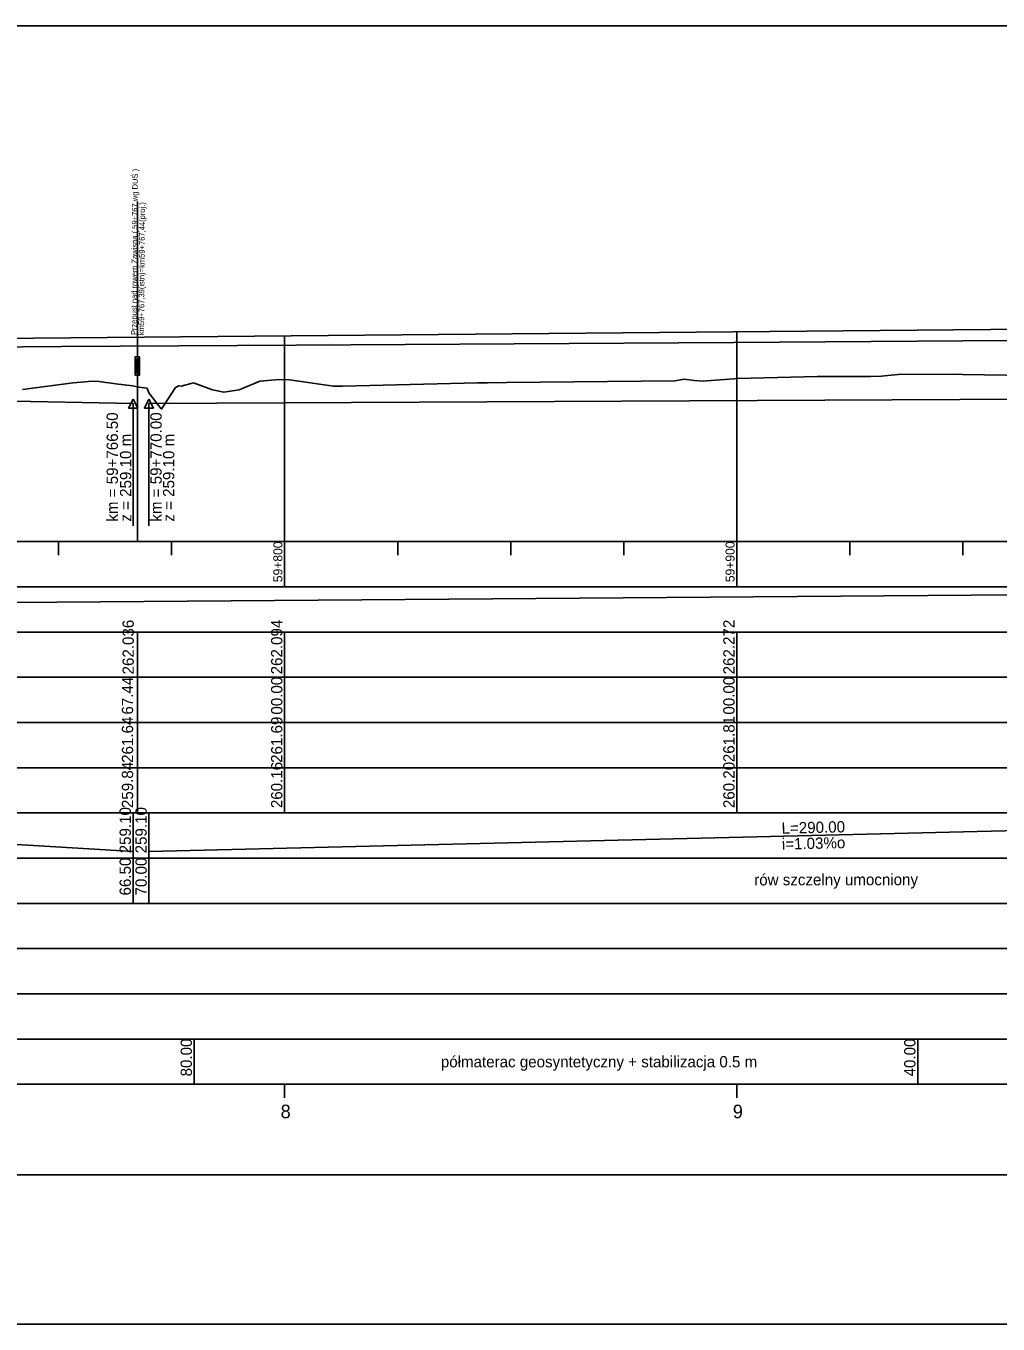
# Model space of a CAD drawing. Extents: x 6445630 to 6518227, y 5499240 to 5511716.
# Drawn here: x 6458974 to 6459189, y 5508418.3 to 5508705.3 of the extents above; entities that cross this region are included whole.
import ezdxf

# ---------------------------------------------------------------- set-up
doc = ezdxf.new("R2010")
doc.units = 0
for name, color, linetype in [('TOR_PROF-obiekty+opisy', 7, 'Continuous'), ('TOR_PROF-opisy pomocnicze', 7, 'Continuous'), ('TOR_PROF-rowy otwarte', 7, 'Continuous'), ('TOR_PROF-tabelka-geometria T1', 7, 'Continuous'), ('TOR_PROF-tabelka-kilometracja', 7, 'Continuous'), ('TOR_PROF-tabelka-odleglosci T1', 7, 'Continuous'), ('TOR_PROF-tabelka-pochylenia proj T1', 7, 'Continuous'), ('TOR_PROF-tabelka-rodzaj rowu T1', 7, 'Continuous'), ('TOR_PROF-tabelka-rowyT1', 7, 'Continuous'), ('TOR_PROF-tabelka-rurociagi T1', 7, 'Continuous'), ('TOR_PROF-tabelka-rzedne istn T1', 7, 'Continuous'), ('TOR_PROF-tabelka-rzedne proj T1', 7, 'Continuous'), ('TOR_PROF-tabelka-teren istniejacy T1', 7, 'Continuous'), ('TOR_PROF-tabelka-warstwa ochronna T1', 7, 'Continuous'), ('TOR_PROF-tor istniejacy T2', 7, 'Continuous'), ('TOR_PROF-tor projektowany', 7, 'Continuous'), ('TOR_PROF-uklad odniesienia', 7, 'Continuous'), ('TOR_PROF-warstwa ochronna', 7, 'Continuous'), ('TOR_RAMKI-dodatkowe3', 7, 'Continuous'), ('TOR_RAMKI-MASKA WYCIECIA', 7, 'Continuous')]:
    doc.layers.add(name, color=color, linetype=linetype)

msp = doc.modelspace()

# ---------------------------------------------------------------- linework, layer by layer
at = {"layer": 'TOR_PROF-obiekty+opisy'}
for p, q in [((6458998.65, 5508591.29), (6458998.65, 5508666.46)), ((6458998.65, 5508657.49), (6458998.65, 5508636.38)), ((6458998.65, 5508657.46), (6458998.65, 5508636.46)), ((6458998.65, 5508657.46), (6458998.65, 5508636.46))]:
    msp.add_line(p, q, dxfattribs=at)
for points in [[(6458999.11, 5508632.14), (6458998.19, 5508632.14), (6458998.19, 5508628.06), (6458999.11, 5508628.06)], [(6458999.03, 5508631.6), (6458998.28, 5508631.6), (6458998.28, 5508628.6), (6458999.03, 5508628.6)]]:
    msp.add_lwpolyline(points, close=True, dxfattribs=at)
for points in [[(6458999.11, 5508628.06), (6458999.11, 5508632.14), (6458998.19, 5508632.14), (6458998.19, 5508628.06), (6458999.11, 5508628.06)], [(6458999.03, 5508628.6), (6458998.28, 5508628.6), (6458998.28, 5508631.6), (6458999.03, 5508631.6), (6458999.03, 5508628.6)]]:
    msp.add_lwpolyline(points, dxfattribs=at)
at = {"layer": 'TOR_PROF-opisy pomocnicze'}
for p, q in [((6458997.71, 5508621.79), (6458997.71, 5508594.79)), ((6459001.21, 5508621.79), (6459001.21, 5508594.79))]:
    msp.add_line(p, q, dxfattribs=at)
for points in [[(6458997.71, 5508622.79), (6458998.71, 5508620.79), (6458996.71, 5508620.79)], [(6459001.21, 5508622.79), (6459002.21, 5508620.79), (6459000.21, 5508620.79)]]:
    msp.add_lwpolyline(points, close=True, dxfattribs=at)
at = {"layer": 'TOR_PROF-rowy otwarte'}
for p, q in [((6458881.21, 5508624.29), (6458997.71, 5508621.79)), ((6459001.21, 5508621.79), (6459291.21, 5508623.29))]:
    msp.add_line(p, q, dxfattribs=at)
at = {"layer": 'TOR_PROF-tabelka-geometria T1'}
for points in [[(6452331.21, 5508451.29), (6462731.21, 5508451.29)], [(6457590.67, 5508451.29), (6459780.93, 5508451.29), (6459780.93, 5508448.62), (6459865.93, 5508448.62), (6459865.93, 5508451.29), (6459945.93, 5508451.29), (6459945.93, 5508453.96), (6460030.94, 5508453.96), (6460030.94, 5508451.29), (6460430.94, 5508451.29), (6460430.94, 5508453.96), (6460512.51, 5508453.96), (6460512.51, 5508451.29), (6460592.51, 5508451.29), (6460592.51, 5508448.62), (6460674.08, 5508448.62), (6460674.08, 5508451.29), (6461733.15, 5508451.29)]]:
    msp.add_lwpolyline(points, dxfattribs=at)
at = {"layer": 'TOR_PROF-tabelka-kilometracja'}
for points in [[(6459031.21, 5508468.29), (6459031.21, 5508471.29)], [(6459131.21, 5508468.29), (6459131.21, 5508471.29)]]:
    msp.add_lwpolyline(points, dxfattribs=at)
at = {"layer": 'TOR_PROF-tabelka-odleglosci T1'}
msp.add_lwpolyline([(6452331.21, 5508551.29), (6462731.21, 5508551.29), (6462731.21, 5508561.29), (6452331.21, 5508561.29)], close=True, dxfattribs=at)
for points in [[(6458998.65, 5508551.29), (6458998.65, 5508561.29)], [(6459031.21, 5508551.29), (6459031.21, 5508561.29)], [(6459131.21, 5508551.29), (6459131.21, 5508561.29)]]:
    msp.add_lwpolyline(points, dxfattribs=at)
at = {"layer": 'TOR_PROF-tabelka-pochylenia proj T1'}
msp.add_lwpolyline([(6452331.21, 5508571.29), (6462731.21, 5508571.29), (6462731.21, 5508581.29), (6452331.21, 5508581.29)], close=True, dxfattribs=at)
msp.add_lwpolyline([(6458316.21, 5508572.79), (6459231.21, 5508579.79)], dxfattribs=at)
at = {"layer": 'TOR_PROF-tabelka-rodzaj rowu T1'}
for points in [[(6452331.21, 5508511.29), (6462731.21, 5508511.29), (6462731.21, 5508521.29), (6452331.21, 5508521.29)], [(6452331.21, 5508511.29), (6462731.21, 5508511.29), (6462731.21, 5508521.29), (6452331.21, 5508521.29)], [(6452331.21, 5508491.29), (6462731.21, 5508491.29), (6462731.21, 5508501.29), (6452331.21, 5508501.29)]]:
    msp.add_lwpolyline(points, close=True, dxfattribs=at)
for points in [[(6458997.71, 5508511.29), (6458997.71, 5508521.29)], [(6459001.21, 5508511.29), (6459001.21, 5508521.29)]]:
    msp.add_lwpolyline(points, dxfattribs=at)
at = {"layer": 'TOR_PROF-tabelka-rowyT1'}
msp.add_lwpolyline([(6452331.21, 5508521.29), (6462731.21, 5508521.29), (6462731.21, 5508531.29), (6452331.21, 5508531.29)], close=True, dxfattribs=at)
msp.add_lwpolyline([(6452331.21, 5508521.29), (6462731.21, 5508521.29), (6462731.21, 5508531.29), (6452331.21, 5508531.29)], close=True, dxfattribs=at)
msp.add_lwpolyline([(6452331.21, 5508521.29), (6462731.21, 5508521.29), (6462731.21, 5508531.29), (6452331.21, 5508531.29)], close=True, dxfattribs=at)
for points in [[(6458881.21, 5508529.79), (6458997.71, 5508522.79)], [(6458997.71, 5508521.29), (6458997.71, 5508531.29)], [(6459001.21, 5508521.29), (6459001.21, 5508531.29)], [(6459001.21, 5508522.79), (6459291.21, 5508529.79)]]:
    msp.add_lwpolyline(points, dxfattribs=at)
at = {"layer": 'TOR_PROF-tabelka-rurociagi T1'}
msp.add_lwpolyline([(6452331.21, 5508501.29), (6462731.21, 5508501.29), (6462731.21, 5508511.29), (6452331.21, 5508511.29)], close=True, dxfattribs=at)
at = {"layer": 'TOR_PROF-tabelka-rzedne istn T1'}
msp.add_lwpolyline([(6452331.21, 5508541.29), (6462731.21, 5508541.29), (6462731.21, 5508551.29), (6452331.21, 5508551.29)], close=True, dxfattribs=at)
for points in [[(6458998.65, 5508541.29), (6458998.65, 5508551.29)], [(6459031.21, 5508541.29), (6459031.21, 5508551.29)], [(6459131.21, 5508541.29), (6459131.21, 5508551.29)], [(6458998.65, 5508531.29), (6458998.65, 5508541.29)], [(6459031.21, 5508531.29), (6459031.21, 5508541.29)], [(6459031.21, 5508531.29), (6459031.21, 5508541.29)], [(6459031.21, 5508531.29), (6459031.21, 5508541.29)], [(6459031.21, 5508531.29), (6459031.21, 5508541.29)], [(6459131.21, 5508531.29), (6459131.21, 5508541.29)], [(6459131.21, 5508531.29), (6459131.21, 5508541.29)], [(6459131.21, 5508531.29), (6459131.21, 5508541.29)], [(6459131.21, 5508531.29), (6459131.21, 5508541.29)]]:
    msp.add_lwpolyline(points, dxfattribs=at)
at = {"layer": 'TOR_PROF-tabelka-rzedne proj T1'}
msp.add_lwpolyline([(6452331.21, 5508561.29), (6462731.21, 5508561.29), (6462731.21, 5508571.29), (6452331.21, 5508571.29)], close=True, dxfattribs=at)
for points in [[(6458998.65, 5508561.29), (6458998.65, 5508571.29)], [(6459031.21, 5508561.29), (6459031.21, 5508571.29)], [(6459131.21, 5508561.29), (6459131.21, 5508571.29)]]:
    msp.add_lwpolyline(points, dxfattribs=at)
at = {"layer": 'TOR_PROF-tabelka-teren istniejacy T1'}
msp.add_lwpolyline([(6452331.21, 5508531.29), (6462731.21, 5508531.29), (6462731.21, 5508541.29), (6452331.21, 5508541.29)], close=True, dxfattribs=at)
msp.add_lwpolyline([(6452331.21, 5508531.29), (6462731.21, 5508531.29), (6462731.21, 5508541.29), (6452331.21, 5508541.29)], close=True, dxfattribs=at)
msp.add_lwpolyline([(6452331.21, 5508531.29), (6462731.21, 5508531.29), (6462731.21, 5508541.29), (6452331.21, 5508541.29)], close=True, dxfattribs=at)
msp.add_lwpolyline([(6452331.21, 5508531.29), (6462731.21, 5508531.29), (6462731.21, 5508541.29), (6452331.21, 5508541.29)], close=True, dxfattribs=at)
at = {"layer": 'TOR_PROF-tabelka-warstwa ochronna T1'}
msp.add_lwpolyline([(6452331.21, 5508481.29), (6462731.21, 5508481.29), (6462731.21, 5508491.29), (6452331.21, 5508491.29)], close=True, dxfattribs=at)
at = {"layer": 'TOR_PROF-tor istniejacy T2'}
msp.add_lwpolyline([(6459879.79, 5508639.74), (6459830.31, 5508639.59), (6459780.15, 5508639.54), (6459763.47, 5508639.39), (6459730.24, 5508639.29), (6459680.5, 5508639.29), (6459630.51, 5508639.04), (6459597.28, 5508638.79), (6459591.3, 5508638.74), (6459558.07, 5508638.59), (6459530.72, 5508638.59), (6459509.57, 5508638.34), (6459476.34, 5508637.94), (6459430.67, 5508637.54), (6459381.22, 5508637.14), (6459331.37, 5508636.74), (6459281.19, 5508636.39), (6459231.27, 5508636.04), (6459181.17, 5508635.64), (6459130.56, 5508635.34), (6459081.98, 5508635.04), (6459033.74, 5508634.74), (6458981.86, 5508634.39), (6458930.5, 5508633.99)], dxfattribs=at)
at = {"layer": 'TOR_PROF-tor projektowany'}
msp.add_line((6458316.21, 5508630.39), (6459231.21, 5508638.54), dxfattribs=at)
msp.add_line((6458316.21, 5508630.39), (6459231.21, 5508638.54), dxfattribs=at)
for points in [[(6459031.21, 5508636.76), (6459031.21, 5508596.29), (6459031.21, 5508591.29), (6459031.21, 5508591.29)], [(6459031.21, 5508636.76), (6459031.21, 5508596.29), (6459031.21, 5508591.29), (6459031.21, 5508591.29)], [(6459131.21, 5508637.65), (6459131.21, 5508596.29), (6459131.21, 5508591.29), (6459131.21, 5508591.29)], [(6459131.21, 5508637.65), (6459131.21, 5508596.29), (6459131.21, 5508591.29), (6459131.21, 5508591.29)]]:
    msp.add_lwpolyline(points, dxfattribs=at)
at = {"layer": 'TOR_PROF-uklad odniesienia'}
for p, q in [((6452331.21, 5508591.29), (6462731.21, 5508591.29)), ((6452331.21, 5508591.29), (6462731.21, 5508591.29)), ((6458981.21, 5508588.29), (6458981.21, 5508591.29)), ((6458981.21, 5508588.29), (6458981.21, 5508591.29)), ((6459006.21, 5508588.29), (6459006.21, 5508591.29)), ((6459006.21, 5508588.29), (6459006.21, 5508591.29)), ((6459031.21, 5508581.29), (6459031.21, 5508591.29)), ((6459031.21, 5508581.29), (6459031.21, 5508591.29)), ((6459056.21, 5508588.29), (6459056.21, 5508591.29)), ((6459056.21, 5508588.29), (6459056.21, 5508591.29)), ((6459081.21, 5508588.29), (6459081.21, 5508591.29)), ((6459081.21, 5508588.29), (6459081.21, 5508591.29)), ((6459106.21, 5508588.29), (6459106.21, 5508591.29)), ((6459106.21, 5508588.29), (6459106.21, 5508591.29)), ((6459131.21, 5508581.29), (6459131.21, 5508591.29)), ((6459131.21, 5508581.29), (6459131.21, 5508591.29)), ((6459156.21, 5508588.29), (6459156.21, 5508591.29)), ((6459156.21, 5508588.29), (6459156.21, 5508591.29)), ((6459181.21, 5508588.29), (6459181.21, 5508591.29)), ((6459181.21, 5508588.29), (6459181.21, 5508591.29))]:
    msp.add_line(p, q, dxfattribs=at)
at = {"layer": 'TOR_PROF-warstwa ochronna'}
msp.add_lwpolyline([(6452331.21, 5508471.29), (6462731.21, 5508471.29), (6462731.21, 5508481.29), (6452331.21, 5508481.29)], close=True, dxfattribs=at)
for points in [[(6459011.21, 5508471.29), (6459011.21, 5508481.29)], [(6459171.21, 5508471.29), (6459171.21, 5508481.29)]]:
    msp.add_lwpolyline(points, dxfattribs=at)
at = {"layer": 'TOR_RAMKI-dodatkowe3'}
for p, q in [((6458973.22, 5508624.93), (6458984.45, 5508626.36)), ((6458984.45, 5508626.36), (6458988.75, 5508626.74)), ((6458988.75, 5508626.74), (6458990.2, 5508626.7)), ((6458990.2, 5508626.7), (6458993.85, 5508626.16)), ((6459008.36, 5508625.63), (6459011.05, 5508626.37)), ((6459011.05, 5508626.37), (6459015.23, 5508624.82)), ((6459021.13, 5508624.85), (6459025.69, 5508626.79)), ((6459025.69, 5508626.79), (6459030.07, 5508627.14)), ((6459030.07, 5508627.14), (6459032.27, 5508627.07)), ((6459032.27, 5508627.07), (6459041.98, 5508625.68)), ((6459044.11, 5508625.68), (6459073.86, 5508626.35)), ((6459073.86, 5508626.35), (6459076.08, 5508626.4)), ((6459076.08, 5508626.4), (6459077.05, 5508626.45)), ((6459077.05, 5508626.45), (6459078.23, 5508626.42)), ((6459078.23, 5508626.42), (6459080.25, 5508626.49)), ((6459080.25, 5508626.49), (6459117.49, 5508626.82)), ((6459117.49, 5508626.82), (6459119.66, 5508627.19)), ((6459119.66, 5508627.19), (6459121.75, 5508626.88)), ((6459121.75, 5508626.88), (6459123.75, 5508626.78)), ((6459123.75, 5508626.78), (6459124.51, 5508626.83)), ((6459124.51, 5508626.83), (6459130.52, 5508627.24)), ((6459130.52, 5508627.24), (6459131.39, 5508627.33)), ((6459131.39, 5508627.33), (6459149.06, 5508627.79)), ((6459149.06, 5508627.79), (6459153.77, 5508627.79)), ((6459153.77, 5508627.79), (6459160.8, 5508627.79)), ((6459160.8, 5508627.79), (6459163.22, 5508627.84)), ((6459163.22, 5508627.84), (6459164.62, 5508627.98)), ((6459164.62, 5508627.98), (6459166.9, 5508628.2)), ((6459166.9, 5508628.2), (6459178.92, 5508628.28)), ((6459178.92, 5508628.28), (6459181.16, 5508628.22)), ((6459181.16, 5508628.22), (6459195.5, 5508627.98)), ((6458993.85, 5508626.16), (6458997.55, 5508625.71)), ((6458997.55, 5508625.71), (6458998.98, 5508625.45)), ((6458998.98, 5508625.45), (6459000.79, 5508625.19)), ((6459000.79, 5508625.19), (6459001.17, 5508624.17)), ((6459001.17, 5508624.17), (6459003.64, 5508621)), ((6459004.37, 5508621.16), (6459007.05, 5508625.34)), ((6459007.05, 5508625.34), (6459007.78, 5508625.72)), ((6459007.78, 5508625.72), (6459008.36, 5508625.63)), ((6459015.23, 5508624.82), (6459017.78, 5508624.32)), ((6459017.78, 5508624.32), (6459021.13, 5508624.85)), ((6459041.98, 5508625.68), (6459042.43, 5508625.64)), ((6459042.43, 5508625.64), (6459042.94, 5508625.64)), ((6459042.94, 5508625.64), (6459044.11, 5508625.68)), ((6459003.64, 5508621), (6459003.94, 5508620.67)), ((6459003.94, 5508620.67), (6459003.99, 5508620.58)), ((6459003.99, 5508620.58), (6459004.37, 5508621.16))]:
    msp.add_line(p, q, dxfattribs=at)
at = {"layer": 'TOR_RAMKI-MASKA WYCIECIA'}
msp.add_lwpolyline([(6457196.67, 5508418.29), (6459246.67, 5508418.29), (6459246.67, 5508705.29), (6457196.67, 5508705.29)], close=True, dxfattribs=at)

# ---------------------------------------------------------------- texts
at = {"layer": 'TOR_PROF-obiekty+opisy'}
for s, p in [('Przepust nad rowem Zawisna ( 59+767 wg DUŚ )', (6458998.5, 5508636.94)), ('km59+767,39(istn)=km59+767,44(proj.)', (6459000.12, 5508636.92))]:
    msp.add_text(s, height=1.25, rotation=89.5846, dxfattribs=at).set_placement(p)
at = {"layer": 'TOR_PROF-opisy pomocnicze'}
for s, p in [('km = 59+766.50', (6458994.34, 5508595.69)), ('km = 59+770.00', (6459004.02, 5508595.69)), ('z = 259.10 m', (6458997.3, 5508595.69)), ('z = 259.10 m', (6459006.81, 5508595.69))]:
    msp.add_text(s, height=2.5, rotation=90, dxfattribs=at).set_placement(p)
at = {"layer": 'TOR_PROF-tabelka-kilometracja'}
for s, p in [('8', (6459030.32, 5508463.79)), ('9', (6459130.32, 5508463.79))]:
    msp.add_text(s, height=3, dxfattribs=at).set_placement(p)
at = {"layer": 'TOR_PROF-tabelka-odleglosci T1'}
for s, p in [('67.44', (6458997.71, 5508553.04)), ('00.00', (6459030.71, 5508553.03)), ('00.00', (6459130.71, 5508553.03))]:
    msp.add_text(s, height=2.5, rotation=90, dxfattribs=at).set_placement(p)
at = {"layer": 'TOR_PROF-tabelka-rodzaj rowu T1'}
for s, p in [('66.50', (6458997.21, 5508513.04)), ('70.00', (6459000.71, 5508513.04))]:
    msp.add_text(s, height=2.5, rotation=90, dxfattribs=at).set_placement(p)
at = {"layer": 'TOR_PROF-tabelka-rowyT1'}
for s, rotation, p in [('259.10', 90, (6458997.21, 5508522.36)), ('259.10', 90, (6459000.71, 5508522.36)), ('L=290.00', 1.3827, (6459141.13, 5508526.67)), ('i=1.03%o', 1.3827, (6459141.19, 5508523.17)), ('rów szczelny umocniony', 0.087, (6459135.05, 5508515.27))]:
    msp.add_text(s, height=2.5, rotation=rotation, dxfattribs=at).set_placement(p)
at = {"layer": 'TOR_PROF-tabelka-rzedne istn T1'}
for s, p in [('261.64', (6458997.71, 5508542.36)), ('261.69', (6459030.71, 5508542.36)), ('261.81', (6459130.71, 5508542.52)), ('259.84', (6458997.71, 5508532.36)), ('260.16', (6459030.71, 5508532.35)), ('260.20', (6459130.71, 5508532.36))]:
    msp.add_text(s, height=2.5, rotation=90, dxfattribs=at).set_placement(p)
at = {"layer": 'TOR_PROF-tabelka-rzedne proj T1'}
for s, p in [('262.036', (6458997.86, 5508561.92)), ('262.094', (6459030.71, 5508561.93)), ('262.272', (6459130.71, 5508561.93))]:
    msp.add_text(s, height=2.5, rotation=90, dxfattribs=at).set_placement(p)
at = {"layer": 'TOR_PROF-uklad odniesienia'}
for s, p in [('59+800', (6459030.71, 5508582.31)), ('59+800', (6459030.71, 5508582.31)), ('59+900', (6459130.71, 5508582.31)), ('59+900', (6459130.71, 5508582.31))]:
    msp.add_text(s, height=2, rotation=90, dxfattribs=at).set_placement(p)
at = {"layer": 'TOR_PROF-warstwa ochronna'}
for s, rotation, p in [('80.00', 90, (6459010.71, 5508473.04)), ('40.00', 90, (6459170.71, 5508473.04)), ('półmaterac geosyntetyczny + stabilizacja 0.5 m', 360, (6459065.75, 5508475.04))]:
    msp.add_text(s, height=2.5, rotation=rotation, dxfattribs=at).set_placement(p)

doc.saveas('drawing.dxf')
